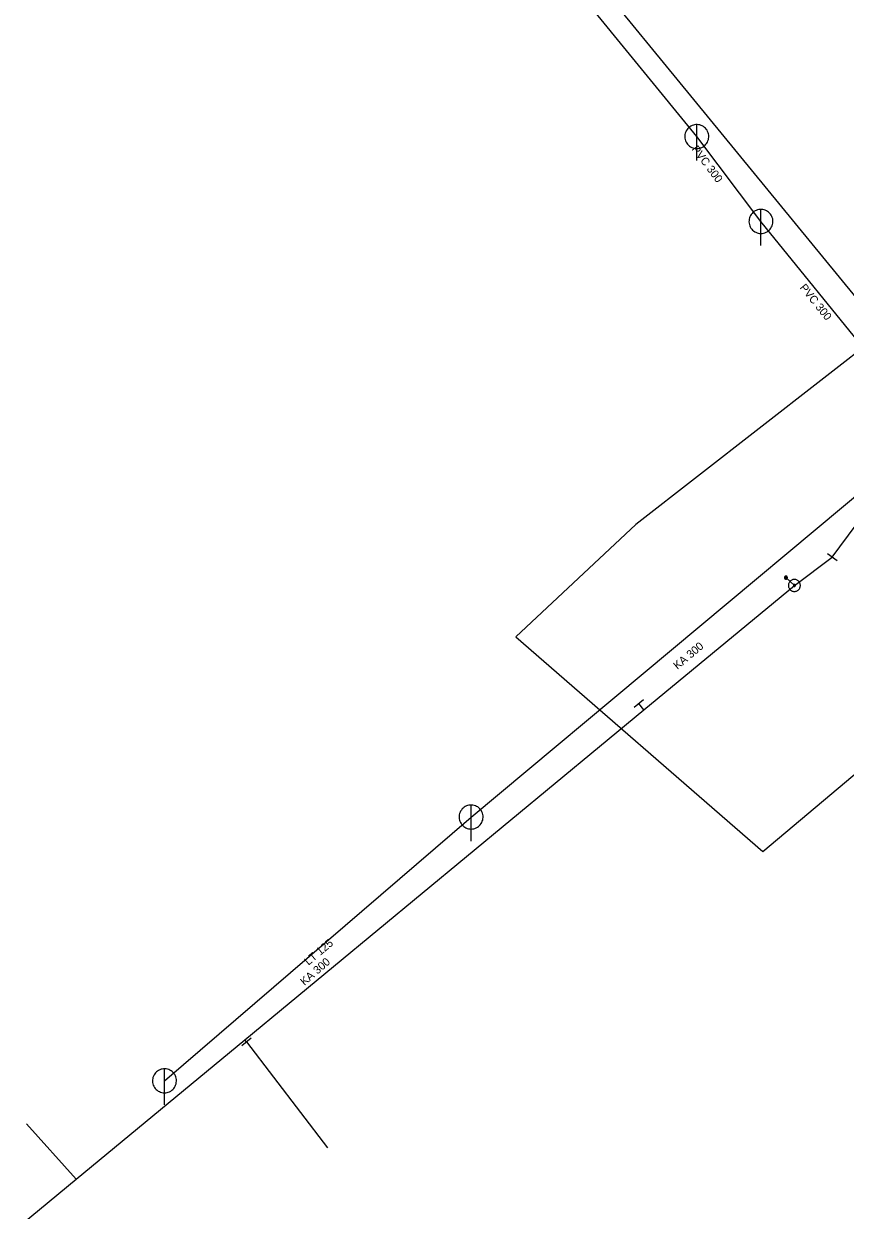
# Model space of a CAD drawing. Extents: x -688296 to -687852, y -973332 to -972816.
# Drawn here: x -688141.5 to -688073, y -973194.3 to -973095.5 of the extents above; entities that cross this region are included whole.
import ezdxf
from ezdxf.enums import TextEntityAlignment as Align

# ---------------------------------------------------------------- set-up
doc = ezdxf.new("R2010")
doc.units = 0
doc.header["$LTSCALE"] = 0.27
for name, color, linetype, lineweight in [('1', 7, 'Continuous', 25), ('13', 7, 'Continuous', 13), ('14', 7, 'Continuous', 13), ('17', 7, 'Continuous', 25), ('22', 7, 'Continuous', 13), ('34', 7, 'Continuous', 13), ('47', 7, 'Continuous', 13), ('9', 7, 'Continuous', 13)]:
    doc.layers.add(name, color=color, linetype=linetype, lineweight=lineweight)

msp = doc.modelspace()

# ---------------------------------------------------------------- linework, layer by layer
at = {"layer": '1'}
msp.add_lwpolyline([(-688090.469, -973137.197), (-688100.452, -973146.564), (-688079.864, -973164.439), (-688061.035, -973148.602), (-688050.242, -973162.551), (-688034.437, -973152.412), (-688045.047, -973140.009), (-687999.652, -973110.475), (-688005.19, -973097.204), (-688023.258, -973110.095), (-688049.335, -973105.21)], close=True, dxfattribs=at)
at = {"layer": '13'}
for p, q in [((-688122.902, -973180.315), (-688116.17, -973189.124)), ((-688137.102, -973191.746), (-688141.248, -973187.122))]:
    msp.add_line(p, q, dxfattribs=at)
at = {"layer": '14', "lineweight": 25}
for p, q in [((-688085.379, -973104.879), (-688102.469, -973083.96)), ((-688080.03, -973111.949), (-688085.379, -973104.879)), ((-688067.26, -973127.699), (-688080.03, -973111.949)), ((-688104.189, -973161.57), (-688065.592, -973129.356)), ((-688129.747, -973183.548), (-688104.189, -973161.57))]:
    msp.add_line(p, q, dxfattribs=at)
at = {"layer": '14'}
for p, q in [((-688077.244, -973142.278), (-688077.947, -973141.624)), ((-688089.804, -973152.646), (-688090.218, -973152.125)), ((-688122.902, -973180.315), (-688123.061, -973180.124))]:
    msp.add_line(p, q, dxfattribs=at)
at = {"layer": '17'}
msp.add_line((-688077.244, -973142.278), (-688074.089, -973139.909), dxfattribs=at)
for points in [[(-688114.989, -973066.03), (-688114.73, -973066.289), (-688065.039, -973126.929)], [(-688074.089, -973139.909), (-688064.727, -973127.319), (-688063.767, -973126.529)], [(-688151.616, -973203.709), (-688137.102, -973191.745), (-688123.061, -973180.124), (-688089.804, -973152.646), (-688077.244, -973142.278)]]:
    msp.add_lwpolyline(points, dxfattribs=at)
at = {"layer": '22'}
for p, q in [((-688085.379, -973106.879), (-688085.378, -973103.879)), ((-688080.03, -973113.949), (-688080.029, -973110.949)), ((-688104.189, -973163.57), (-688104.188, -973160.57)), ((-688129.747, -973185.548), (-688129.746, -973182.548))]:
    msp.add_line(p, q, dxfattribs=at)
for points in [[(-688084.379, -973104.879), (-688084.384, -973104.77), (-688084.402, -973104.662), (-688084.432, -973104.556), (-688084.472, -973104.455), (-688084.524, -973104.358), (-688084.586, -973104.268), (-688084.658, -973104.185), (-688084.738, -973104.111), (-688084.826, -973104.045), (-688084.92, -973103.99), (-688085.02, -973103.945), (-688085.125, -973103.912), (-688085.232, -973103.89), (-688085.341, -973103.88), (-688085.451, -973103.882), (-688085.559, -973103.896), (-688085.666, -973103.921), (-688085.769, -973103.958), (-688085.867, -973104.007), (-688085.959, -973104.065), (-688086.045, -973104.134), (-688086.122, -973104.211), (-688086.191, -973104.297), (-688086.25, -973104.389), (-688086.298, -973104.487), (-688086.335, -973104.59), (-688086.361, -973104.697), (-688086.375, -973104.805), (-688086.378, -973104.915), (-688086.368, -973105.024), (-688086.347, -973105.131), (-688086.313, -973105.235), (-688086.269, -973105.335), (-688086.214, -973105.43), (-688086.148, -973105.518), (-688086.074, -973105.598), (-688085.991, -973105.67), (-688085.901, -973105.732), (-688085.805, -973105.784), (-688085.703, -973105.825), (-688085.598, -973105.855), (-688085.49, -973105.873), (-688085.38, -973105.879), (-688085.271, -973105.873), (-688085.163, -973105.855), (-688085.058, -973105.826), (-688084.956, -973105.785), (-688084.859, -973105.733), (-688084.769, -973105.671), (-688084.686, -973105.6), (-688084.611, -973105.52), (-688084.546, -973105.432), (-688084.49, -973105.338), (-688084.446, -973105.238), (-688084.412, -973105.134), (-688084.39, -973105.026), (-688084.38, -973104.917)], [(-688079.03, -973111.949), (-688079.035, -973111.84), (-688079.053, -973111.732), (-688079.083, -973111.626), (-688079.123, -973111.525), (-688079.175, -973111.428), (-688079.237, -973111.338), (-688079.309, -973111.255), (-688079.389, -973111.181), (-688079.477, -973111.115), (-688079.571, -973111.06), (-688079.671, -973111.015), (-688079.776, -973110.982), (-688079.883, -973110.96), (-688079.992, -973110.95), (-688080.102, -973110.952), (-688080.21, -973110.966), (-688080.317, -973110.991), (-688080.42, -973111.028), (-688080.518, -973111.077), (-688080.61, -973111.135), (-688080.696, -973111.204), (-688080.773, -973111.281), (-688080.842, -973111.367), (-688080.901, -973111.459), (-688080.949, -973111.557), (-688080.986, -973111.66), (-688081.012, -973111.767), (-688081.026, -973111.875), (-688081.029, -973111.985), (-688081.019, -973112.094), (-688080.998, -973112.201), (-688080.964, -973112.305), (-688080.92, -973112.405), (-688080.865, -973112.5), (-688080.799, -973112.588), (-688080.725, -973112.668), (-688080.642, -973112.74), (-688080.552, -973112.802), (-688080.456, -973112.854), (-688080.354, -973112.895), (-688080.249, -973112.925), (-688080.141, -973112.943), (-688080.031, -973112.949), (-688079.922, -973112.943), (-688079.814, -973112.925), (-688079.709, -973112.896), (-688079.607, -973112.855), (-688079.51, -973112.803), (-688079.42, -973112.741), (-688079.337, -973112.67), (-688079.262, -973112.59), (-688079.197, -973112.502), (-688079.141, -973112.408), (-688079.097, -973112.308), (-688079.063, -973112.204), (-688079.041, -973112.096), (-688079.031, -973111.987)], [(-688103.189, -973161.57), (-688103.194, -973161.461), (-688103.212, -973161.353), (-688103.242, -973161.247), (-688103.282, -973161.146), (-688103.334, -973161.049), (-688103.396, -973160.959), (-688103.468, -973160.876), (-688103.548, -973160.802), (-688103.636, -973160.736), (-688103.73, -973160.681), (-688103.83, -973160.636), (-688103.935, -973160.603), (-688104.042, -973160.581), (-688104.151, -973160.571), (-688104.261, -973160.573), (-688104.369, -973160.587), (-688104.476, -973160.612), (-688104.579, -973160.649), (-688104.677, -973160.698), (-688104.769, -973160.756), (-688104.855, -973160.825), (-688104.932, -973160.902), (-688105.001, -973160.988), (-688105.06, -973161.08), (-688105.108, -973161.178), (-688105.145, -973161.281), (-688105.171, -973161.388), (-688105.185, -973161.496), (-688105.188, -973161.606), (-688105.178, -973161.715), (-688105.157, -973161.822), (-688105.123, -973161.926), (-688105.079, -973162.026), (-688105.024, -973162.121), (-688104.958, -973162.209), (-688104.884, -973162.289), (-688104.801, -973162.361), (-688104.711, -973162.423), (-688104.615, -973162.475), (-688104.513, -973162.516), (-688104.408, -973162.546), (-688104.3, -973162.564), (-688104.19, -973162.57), (-688104.081, -973162.564), (-688103.973, -973162.546), (-688103.868, -973162.517), (-688103.766, -973162.476), (-688103.669, -973162.424), (-688103.579, -973162.362), (-688103.496, -973162.291), (-688103.421, -973162.211), (-688103.356, -973162.123), (-688103.3, -973162.029), (-688103.256, -973161.929), (-688103.222, -973161.825), (-688103.2, -973161.717), (-688103.19, -973161.608)], [(-688128.747, -973183.548), (-688128.752, -973183.439), (-688128.77, -973183.331), (-688128.8, -973183.225), (-688128.84, -973183.124), (-688128.892, -973183.027), (-688128.954, -973182.937), (-688129.026, -973182.854), (-688129.106, -973182.78), (-688129.194, -973182.714), (-688129.288, -973182.659), (-688129.388, -973182.614), (-688129.493, -973182.581), (-688129.6, -973182.559), (-688129.709, -973182.549), (-688129.819, -973182.551), (-688129.927, -973182.565), (-688130.034, -973182.59), (-688130.137, -973182.627), (-688130.235, -973182.676), (-688130.327, -973182.734), (-688130.413, -973182.803), (-688130.49, -973182.88), (-688130.559, -973182.966), (-688130.618, -973183.058), (-688130.666, -973183.156), (-688130.703, -973183.259), (-688130.729, -973183.366), (-688130.743, -973183.474), (-688130.746, -973183.584), (-688130.736, -973183.693), (-688130.715, -973183.8), (-688130.681, -973183.904), (-688130.637, -973184.004), (-688130.582, -973184.099), (-688130.516, -973184.187), (-688130.442, -973184.267), (-688130.359, -973184.339), (-688130.269, -973184.401), (-688130.173, -973184.453), (-688130.071, -973184.494), (-688129.966, -973184.524), (-688129.858, -973184.542), (-688129.748, -973184.548), (-688129.639, -973184.542), (-688129.531, -973184.524), (-688129.426, -973184.495), (-688129.324, -973184.454), (-688129.227, -973184.402), (-688129.137, -973184.34), (-688129.054, -973184.269), (-688128.979, -973184.189), (-688128.914, -973184.101), (-688128.858, -973184.007), (-688128.814, -973183.907), (-688128.78, -973183.803), (-688128.758, -973183.695), (-688128.748, -973183.586)]]:
    msp.add_lwpolyline(points, close=True, dxfattribs=at)
at = {"layer": '34'}
for p, q in [((-688074.49, -973139.611), (-688073.688, -973140.207)), ((-688089.827, -973151.812), (-688090.609, -973152.436)), ((-688122.516, -973179.996), (-688123.287, -973180.633))]:
    msp.add_line(p, q, dxfattribs=at)
at = {"layer": '47'}
for points in [[(-688076.854, -973141.963), (-688076.889, -973141.925), (-688076.928, -973141.889), (-688076.971, -973141.859), (-688077.015, -973141.832), (-688077.064, -973141.811), (-688077.114, -973141.795), (-688077.165, -973141.785), (-688077.217, -973141.779), (-688077.269, -973141.778), (-688077.321, -973141.784), (-688077.373, -973141.794), (-688077.422, -973141.811), (-688077.47, -973141.832), (-688077.515, -973141.858), (-688077.558, -973141.888), (-688077.596, -973141.923), (-688077.632, -973141.962), (-688077.663, -973142.005), (-688077.689, -973142.049), (-688077.71, -973142.098), (-688077.726, -973142.148), (-688077.737, -973142.199), (-688077.743, -973142.251), (-688077.743, -973142.303), (-688077.737, -973142.355), (-688077.727, -973142.407), (-688077.711, -973142.457), (-688077.689, -973142.504), (-688077.663, -973142.549), (-688077.633, -973142.592), (-688077.598, -973142.63), (-688077.559, -973142.666), (-688077.516, -973142.697), (-688077.472, -973142.723), (-688077.423, -973142.744), (-688077.374, -973142.761), (-688077.322, -973142.772), (-688077.27, -973142.777), (-688077.218, -973142.777), (-688077.166, -973142.771), (-688077.114, -973142.761), (-688077.065, -973142.745), (-688077.017, -973142.723), (-688076.972, -973142.697), (-688076.929, -973142.667), (-688076.891, -973142.632), (-688076.855, -973142.593), (-688076.825, -973142.551), (-688076.798, -973142.506), (-688076.777, -973142.457), (-688076.76, -973142.408), (-688076.75, -973142.357), (-688076.744, -973142.305), (-688076.744, -973142.252), (-688076.75, -973142.2), (-688076.76, -973142.148), (-688076.777, -973142.1), (-688076.798, -973142.051), (-688076.824, -973142.006)], [(-688077.18, -973142.226), (-688077.185, -973142.219), (-688077.192, -973142.214), (-688077.199, -973142.209), (-688077.206, -973142.205), (-688077.214, -973142.201), (-688077.222, -973142.199), (-688077.231, -973142.196), (-688077.239, -973142.195), (-688077.248, -973142.196), (-688077.256, -973142.197), (-688077.265, -973142.198), (-688077.273, -973142.201), (-688077.281, -973142.205), (-688077.288, -973142.208), (-688077.295, -973142.214), (-688077.302, -973142.219), (-688077.307, -973142.226), (-688077.312, -973142.233), (-688077.316, -973142.24), (-688077.32, -973142.248), (-688077.322, -973142.256), (-688077.325, -973142.265), (-688077.326, -973142.273), (-688077.326, -973142.282), (-688077.324, -973142.29), (-688077.323, -973142.299), (-688077.32, -973142.307), (-688077.316, -973142.315), (-688077.313, -973142.322), (-688077.307, -973142.329), (-688077.302, -973142.336), (-688077.295, -973142.341), (-688077.288, -973142.346), (-688077.281, -973142.35), (-688077.273, -973142.354), (-688077.265, -973142.357), (-688077.256, -973142.359), (-688077.248, -973142.36), (-688077.239, -973142.36), (-688077.231, -973142.358), (-688077.222, -973142.357), (-688077.214, -973142.354), (-688077.206, -973142.35), (-688077.199, -973142.347), (-688077.192, -973142.341), (-688077.185, -973142.336), (-688077.18, -973142.329), (-688077.175, -973142.322), (-688077.171, -973142.315), (-688077.167, -973142.307), (-688077.164, -973142.299), (-688077.162, -973142.29), (-688077.161, -973142.282), (-688077.162, -973142.273), (-688077.163, -973142.265), (-688077.164, -973142.256), (-688077.167, -973142.248), (-688077.171, -973142.24), (-688077.174, -973142.233)]]:
    msp.add_lwpolyline(points, close=True, dxfattribs=at)
at = {"layer": '9'}
for points in [[(-688078.073, -973141.624), (-688078.073, -973141.637), (-688078.071, -973141.65), (-688078.068, -973141.663), (-688078.063, -973141.675), (-688078.057, -973141.687), (-688078.05, -973141.698), (-688078.042, -973141.708), (-688078.032, -973141.718), (-688078.022, -973141.726), (-688078.011, -973141.733), (-688077.999, -973141.739), (-688077.987, -973141.744), (-688077.974, -973141.747), (-688077.961, -973141.749), (-688077.948, -973141.751), (-688077.935, -973141.75), (-688077.922, -973141.748), (-688077.909, -973141.745), (-688077.897, -973141.74), (-688077.885, -973141.734), (-688077.874, -973141.727), (-688077.864, -973141.719), (-688077.854, -973141.709), (-688077.846, -973141.699), (-688077.839, -973141.688), (-688077.833, -973141.676), (-688077.828, -973141.664), (-688077.825, -973141.651), (-688077.823, -973141.638), (-688077.821, -973141.625), (-688077.822, -973141.612), (-688077.824, -973141.599), (-688077.827, -973141.586), (-688077.832, -973141.574), (-688077.838, -973141.562), (-688077.845, -973141.551), (-688077.853, -973141.541), (-688077.863, -973141.531), (-688077.873, -973141.523), (-688077.884, -973141.516), (-688077.896, -973141.51), (-688077.908, -973141.505), (-688077.921, -973141.502), (-688077.934, -973141.5), (-688077.947, -973141.499), (-688077.96, -973141.499), (-688077.973, -973141.501), (-688077.986, -973141.504), (-688077.998, -973141.509), (-688078.01, -973141.515), (-688078.021, -973141.522), (-688078.031, -973141.53), (-688078.041, -973141.54), (-688078.049, -973141.55), (-688078.056, -973141.561), (-688078.062, -973141.573), (-688078.067, -973141.585), (-688078.07, -973141.598), (-688078.072, -973141.611)], [(-688078.053, -973141.624), (-688078.054, -973141.635), (-688078.052, -973141.646), (-688078.049, -973141.657), (-688078.045, -973141.667), (-688078.04, -973141.677), (-688078.034, -973141.686), (-688078.027, -973141.695), (-688078.019, -973141.703), (-688078.01, -973141.71), (-688078.001, -973141.716), (-688077.991, -973141.721), (-688077.981, -973141.725), (-688077.97, -973141.728), (-688077.959, -973141.731), (-688077.948, -973141.731), (-688077.937, -973141.731), (-688077.926, -973141.729), (-688077.915, -973141.726), (-688077.905, -973141.722), (-688077.895, -973141.717), (-688077.886, -973141.711), (-688077.877, -973141.704), (-688077.869, -973141.696), (-688077.862, -973141.687), (-688077.856, -973141.678), (-688077.851, -973141.668), (-688077.847, -973141.658), (-688077.844, -973141.647), (-688077.842, -973141.636), (-688077.841, -973141.625), (-688077.841, -973141.614), (-688077.843, -973141.603), (-688077.846, -973141.592), (-688077.85, -973141.582), (-688077.855, -973141.572), (-688077.861, -973141.563), (-688077.868, -973141.554), (-688077.876, -973141.546), (-688077.885, -973141.539), (-688077.894, -973141.533), (-688077.904, -973141.528), (-688077.914, -973141.524), (-688077.925, -973141.521), (-688077.936, -973141.519), (-688077.947, -973141.519), (-688077.958, -973141.518), (-688077.969, -973141.52), (-688077.98, -973141.523), (-688077.99, -973141.527), (-688078, -973141.532), (-688078.009, -973141.538), (-688078.018, -973141.545), (-688078.026, -973141.553), (-688078.033, -973141.562), (-688078.039, -973141.571), (-688078.044, -973141.581), (-688078.048, -973141.591), (-688078.051, -973141.602), (-688078.053, -973141.613)], [(-688078.034, -973141.624), (-688078.034, -973141.633), (-688078.033, -973141.642), (-688078.03, -973141.651), (-688078.027, -973141.659), (-688078.023, -973141.667), (-688078.018, -973141.675), (-688078.012, -973141.682), (-688078.006, -973141.688), (-688077.999, -973141.694), (-688077.991, -973141.699), (-688077.983, -973141.703), (-688077.975, -973141.706), (-688077.966, -973141.709), (-688077.957, -973141.71), (-688077.948, -973141.712), (-688077.939, -973141.711), (-688077.93, -973141.71), (-688077.921, -973141.707), (-688077.913, -973141.704), (-688077.905, -973141.7), (-688077.897, -973141.695), (-688077.89, -973141.689), (-688077.884, -973141.683), (-688077.878, -973141.676), (-688077.873, -973141.668), (-688077.869, -973141.66), (-688077.866, -973141.652), (-688077.863, -973141.643), (-688077.862, -973141.634), (-688077.86, -973141.625), (-688077.861, -973141.616), (-688077.862, -973141.607), (-688077.865, -973141.598), (-688077.868, -973141.59), (-688077.872, -973141.582), (-688077.877, -973141.574), (-688077.883, -973141.567), (-688077.889, -973141.561), (-688077.896, -973141.555), (-688077.904, -973141.55), (-688077.912, -973141.546), (-688077.92, -973141.543), (-688077.929, -973141.54), (-688077.938, -973141.539), (-688077.947, -973141.538), (-688077.956, -973141.538), (-688077.965, -973141.539), (-688077.974, -973141.542), (-688077.982, -973141.545), (-688077.99, -973141.549), (-688077.998, -973141.554), (-688078.005, -973141.56), (-688078.011, -973141.566), (-688078.017, -973141.573), (-688078.022, -973141.581), (-688078.026, -973141.589), (-688078.029, -973141.597), (-688078.032, -973141.606), (-688078.033, -973141.615)], [(-688078.014, -973141.624), (-688078.014, -973141.631), (-688078.013, -973141.638), (-688078.012, -973141.645), (-688078.009, -973141.651), (-688078.006, -973141.657), (-688078.002, -973141.663), (-688077.998, -973141.669), (-688077.993, -973141.674), (-688077.987, -973141.678), (-688077.981, -973141.682), (-688077.975, -973141.685), (-688077.969, -973141.688), (-688077.962, -973141.689), (-688077.955, -973141.692), (-688077.948, -973141.692), (-688077.941, -973141.692), (-688077.934, -973141.69), (-688077.927, -973141.689), (-688077.921, -973141.686), (-688077.914, -973141.683), (-688077.909, -973141.679), (-688077.903, -973141.675), (-688077.898, -973141.67), (-688077.894, -973141.664), (-688077.89, -973141.658), (-688077.887, -973141.652), (-688077.884, -973141.646), (-688077.882, -973141.639), (-688077.881, -973141.632), (-688077.88, -973141.625), (-688077.88, -973141.618), (-688077.881, -973141.611), (-688077.883, -973141.604), (-688077.886, -973141.598), (-688077.889, -973141.591), (-688077.893, -973141.586), (-688077.897, -973141.58), (-688077.902, -973141.575), (-688077.908, -973141.571), (-688077.913, -973141.567), (-688077.92, -973141.564), (-688077.926, -973141.561), (-688077.933, -973141.559), (-688077.94, -973141.558), (-688077.947, -973141.558), (-688077.954, -973141.558), (-688077.961, -973141.558), (-688077.968, -973141.56), (-688077.974, -973141.563), (-688077.98, -973141.566), (-688077.986, -973141.57), (-688077.992, -973141.574), (-688077.997, -973141.579), (-688078.001, -973141.585), (-688078.005, -973141.59), (-688078.008, -973141.597), (-688078.011, -973141.603), (-688078.012, -973141.61), (-688078.014, -973141.617)], [(-688077.994, -973141.624), (-688077.994, -973141.629), (-688077.994, -973141.634), (-688077.993, -973141.639), (-688077.991, -973141.643), (-688077.989, -973141.648), (-688077.986, -973141.652), (-688077.983, -973141.655), (-688077.979, -973141.659), (-688077.976, -973141.662), (-688077.972, -973141.665), (-688077.967, -973141.667), (-688077.963, -973141.669), (-688077.958, -973141.67), (-688077.953, -973141.672), (-688077.948, -973141.672), (-688077.943, -973141.672), (-688077.938, -973141.671), (-688077.933, -973141.67), (-688077.929, -973141.668), (-688077.924, -973141.666), (-688077.92, -973141.663), (-688077.916, -973141.66), (-688077.913, -973141.656), (-688077.91, -973141.653), (-688077.907, -973141.649), (-688077.905, -973141.644), (-688077.903, -973141.64), (-688077.902, -973141.635), (-688077.901, -973141.63), (-688077.9, -973141.625), (-688077.9, -973141.62), (-688077.901, -973141.615), (-688077.902, -973141.61), (-688077.904, -973141.606), (-688077.906, -973141.601), (-688077.909, -973141.597), (-688077.912, -973141.593), (-688077.915, -973141.59), (-688077.919, -973141.587), (-688077.923, -973141.584), (-688077.928, -973141.582), (-688077.932, -973141.58), (-688077.937, -973141.579), (-688077.942, -973141.578), (-688077.947, -973141.578), (-688077.952, -973141.578), (-688077.957, -973141.579), (-688077.962, -973141.579), (-688077.966, -973141.581), (-688077.971, -973141.583), (-688077.975, -973141.586), (-688077.978, -973141.589), (-688077.982, -973141.592), (-688077.985, -973141.596), (-688077.988, -973141.6), (-688077.99, -973141.605), (-688077.992, -973141.609), (-688077.993, -973141.614), (-688077.994, -973141.619)], [(-688077.974, -973141.624), (-688077.974, -973141.627), (-688077.975, -973141.63), (-688077.974, -973141.632), (-688077.973, -973141.635), (-688077.972, -973141.638), (-688077.97, -973141.64), (-688077.968, -973141.642), (-688077.966, -973141.644), (-688077.964, -973141.646), (-688077.962, -973141.648), (-688077.959, -973141.65), (-688077.956, -973141.651), (-688077.954, -973141.651), (-688077.951, -973141.652), (-688077.948, -973141.652), (-688077.945, -973141.652), (-688077.942, -973141.652), (-688077.939, -973141.651), (-688077.937, -973141.65), (-688077.934, -973141.649), (-688077.932, -973141.647), (-688077.929, -973141.645), (-688077.927, -973141.643), (-688077.926, -973141.641), (-688077.924, -973141.639), (-688077.923, -973141.636), (-688077.921, -973141.633), (-688077.921, -973141.631), (-688077.92, -973141.628), (-688077.919, -973141.625), (-688077.92, -973141.622), (-688077.92, -973141.619), (-688077.921, -973141.616), (-688077.922, -973141.614), (-688077.923, -973141.611), (-688077.925, -973141.609), (-688077.926, -973141.606), (-688077.928, -973141.604), (-688077.931, -973141.603), (-688077.933, -973141.601), (-688077.936, -973141.6), (-688077.938, -973141.599), (-688077.941, -973141.598), (-688077.944, -973141.598), (-688077.947, -973141.597), (-688077.95, -973141.598), (-688077.953, -973141.597), (-688077.955, -973141.599), (-688077.958, -973141.599), (-688077.961, -973141.6), (-688077.963, -973141.602), (-688077.965, -973141.603), (-688077.967, -973141.605), (-688077.969, -973141.608), (-688077.971, -973141.61), (-688077.972, -973141.613), (-688077.973, -973141.615), (-688077.974, -973141.618), (-688077.974, -973141.621)], [(-688077.955, -973141.624), (-688077.955, -973141.626), (-688077.955, -973141.626), (-688077.954, -973141.626), (-688077.954, -973141.628), (-688077.955, -973141.629), (-688077.953, -973141.629), (-688077.953, -973141.629), (-688077.953, -973141.631), (-688077.953, -973141.631), (-688077.952, -973141.632), (-688077.95, -973141.632), (-688077.95, -973141.632), (-688077.95, -973141.633), (-688077.948, -973141.633), (-688077.948, -973141.633), (-688077.947, -973141.633), (-688077.946, -973141.633), (-688077.946, -973141.632), (-688077.945, -973141.632), (-688077.943, -973141.632), (-688077.943, -973141.631), (-688077.943, -973141.631), (-688077.942, -973141.63), (-688077.942, -973141.63), (-688077.94, -973141.629), (-688077.94, -973141.628), (-688077.939, -973141.627), (-688077.939, -973141.627), (-688077.939, -973141.626), (-688077.939, -973141.625), (-688077.939, -973141.624), (-688077.939, -973141.623), (-688077.939, -973141.623), (-688077.94, -973141.622), (-688077.94, -973141.621), (-688077.941, -973141.62), (-688077.941, -973141.62), (-688077.942, -973141.619), (-688077.942, -973141.619), (-688077.943, -973141.618), (-688077.944, -973141.618), (-688077.945, -973141.617), (-688077.945, -973141.617), (-688077.946, -973141.617), (-688077.947, -973141.617), (-688077.948, -973141.617), (-688077.949, -973141.617), (-688077.949, -973141.617), (-688077.95, -973141.618), (-688077.951, -973141.617), (-688077.952, -973141.619), (-688077.952, -973141.619), (-688077.953, -973141.619), (-688077.953, -973141.619), (-688077.954, -973141.621), (-688077.954, -973141.622), (-688077.954, -973141.623), (-688077.955, -973141.623), (-688077.955, -973141.624)]]:
    msp.add_lwpolyline(points, close=True, dxfattribs=at)

# ---------------------------------------------------------------- texts
at = {"layer": '1'}
for s, rotation, p in [('PVC 300 ', 307, (-688084.6948, -973107.4581)), ('PVC 300 ', 307, (-688084.6948, -973107.4581)), ('PVC 300 ', 307, (-688084.6948, -973107.4581)), ('PVC 300 ', 307, (-688084.6948, -973107.4581)), ('PVC 300 ', 307, (-688084.6948, -973107.4581)), ('PVC 300 ', 309, (-688075.6363, -973118.967)), ('PVC 300 ', 309, (-688075.6363, -973118.967)), ('PVC 300 ', 309, (-688075.6363, -973118.967)), ('PVC 300 ', 309, (-688075.6363, -973118.967)), ('PVC 300 ', 309, (-688075.6363, -973118.967)), ('KA 300', 40, (-688085.8695, -973148.3789)), ('KA 300', 40, (-688085.8695, -973148.3789)), ('KA 300', 40, (-688085.8695, -973148.3789)), ('KA 300', 40, (-688085.8695, -973148.3789)), ('KA 300', 40, (-688085.8695, -973148.3789)), ('LT 125', 40, (-688116.6852, -973173.0737)), ('LT 125', 40, (-688116.6852, -973173.0737)), ('LT 125', 40, (-688116.6852, -973173.0737)), ('LT 125', 40, (-688116.6852, -973173.0737)), ('LT 125', 40, (-688116.6852, -973173.0737)), ('KA 300', 41, (-688116.9731, -973174.6915)), ('KA 300', 41, (-688116.9731, -973174.6915)), ('KA 300', 41, (-688116.9731, -973174.6915)), ('KA 300', 41, (-688116.9731, -973174.6915)), ('KA 300', 41, (-688116.9731, -973174.6915))]:
    msp.add_text(s, height=0.6667, rotation=rotation, dxfattribs=at).set_placement(p, align=Align.CENTER)

doc.saveas('drawing.dxf')
